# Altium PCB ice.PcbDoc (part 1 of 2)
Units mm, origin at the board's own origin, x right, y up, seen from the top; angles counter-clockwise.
Board outline 65 x 30 mm, 4 copper layers (L1 [TOP], L2 [GND], L3[PWR], L4 [BOTTOM]), stack 1.49 mm thick; 140 components, 110 nets, 478 pads, 226 vias.
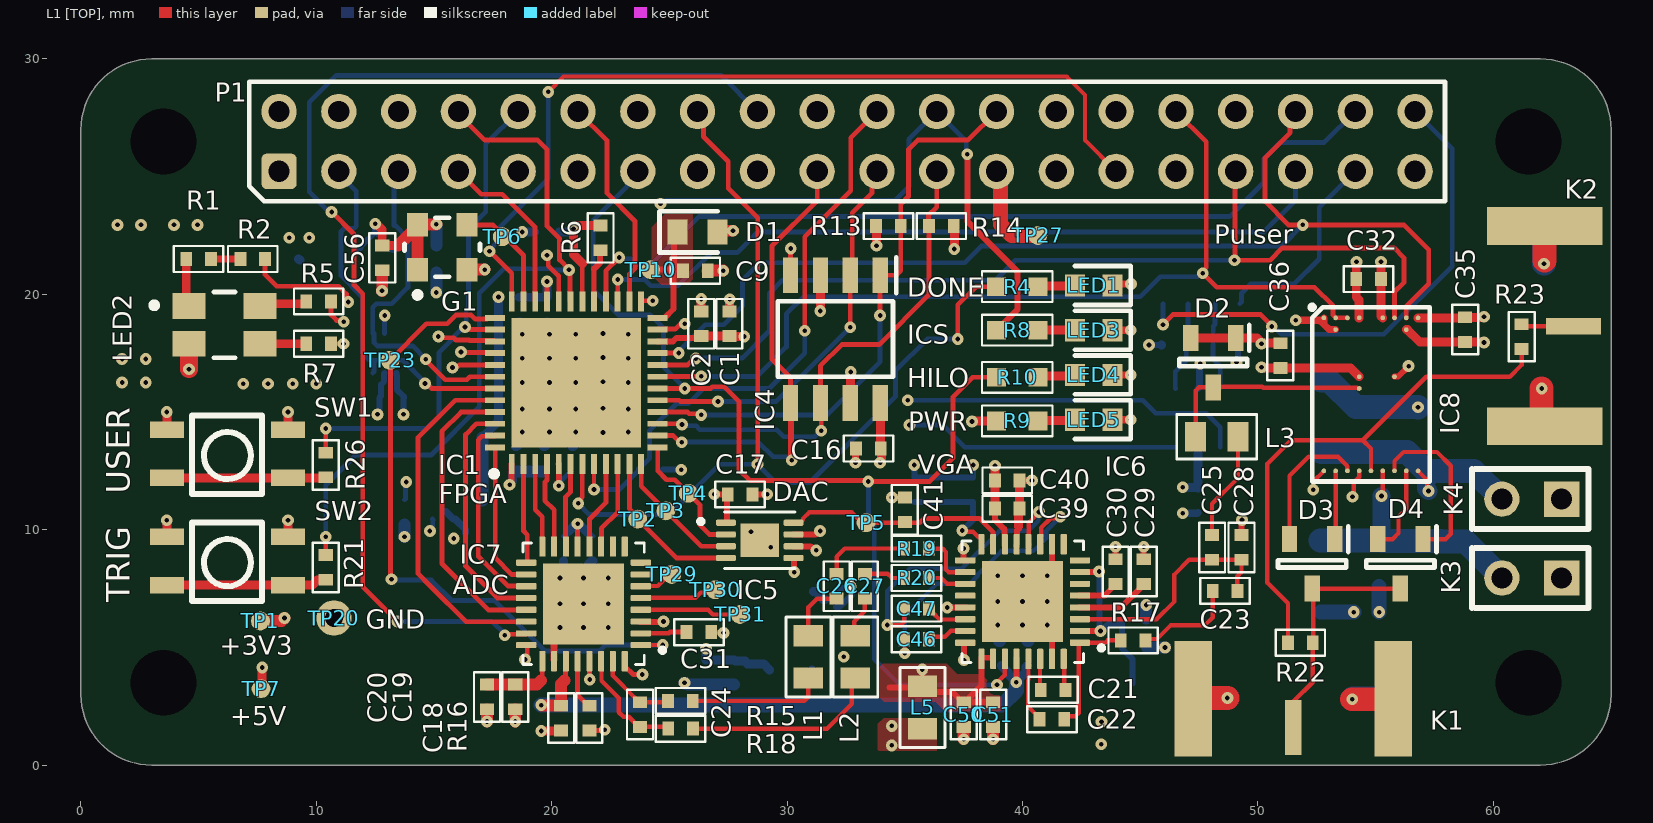
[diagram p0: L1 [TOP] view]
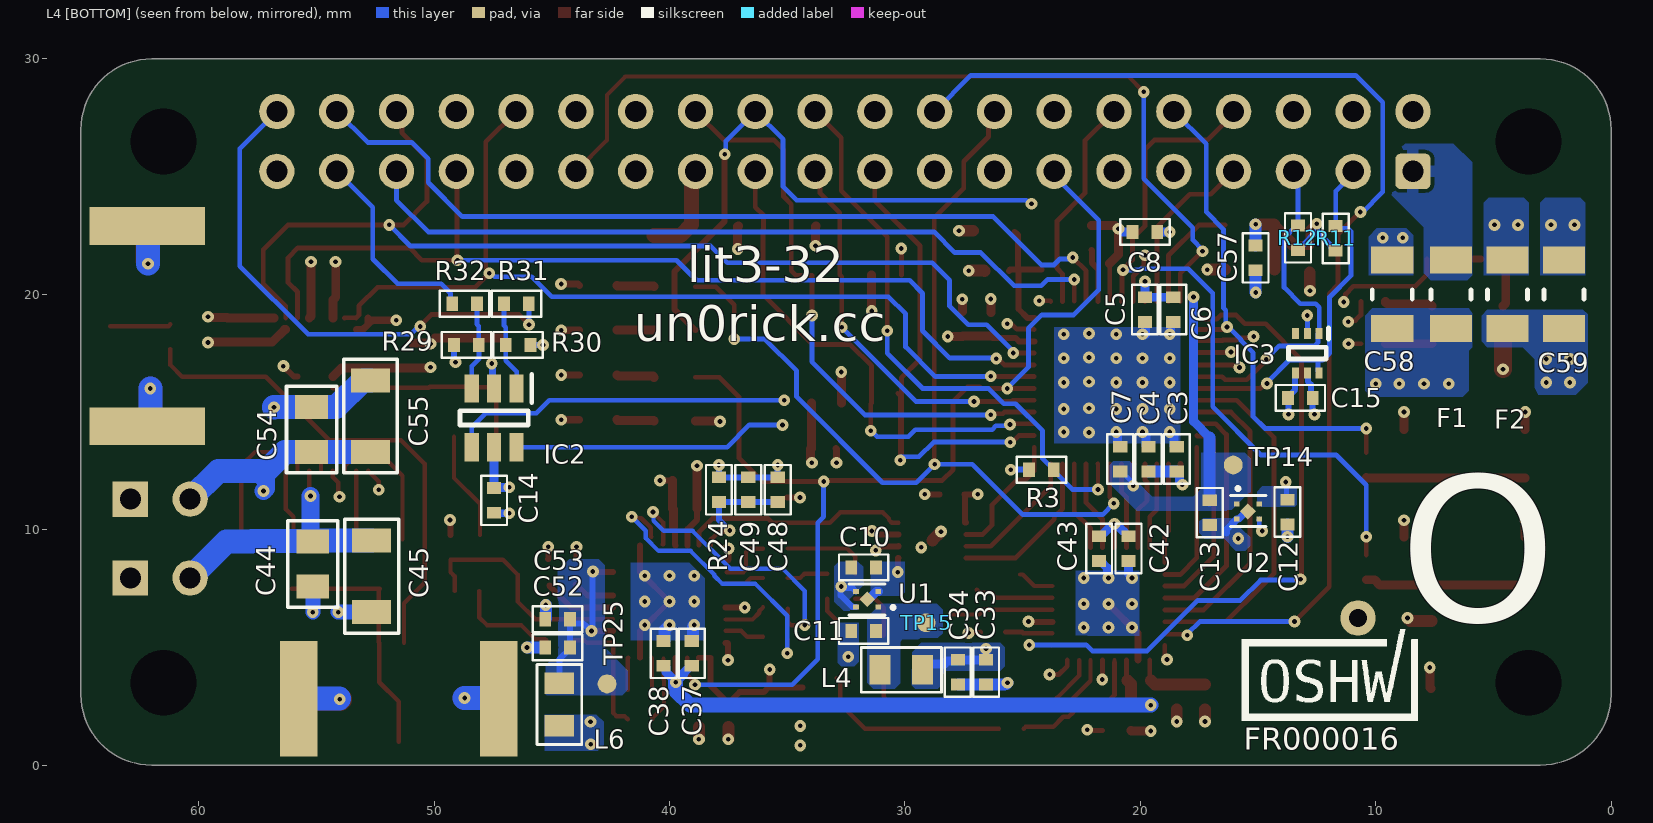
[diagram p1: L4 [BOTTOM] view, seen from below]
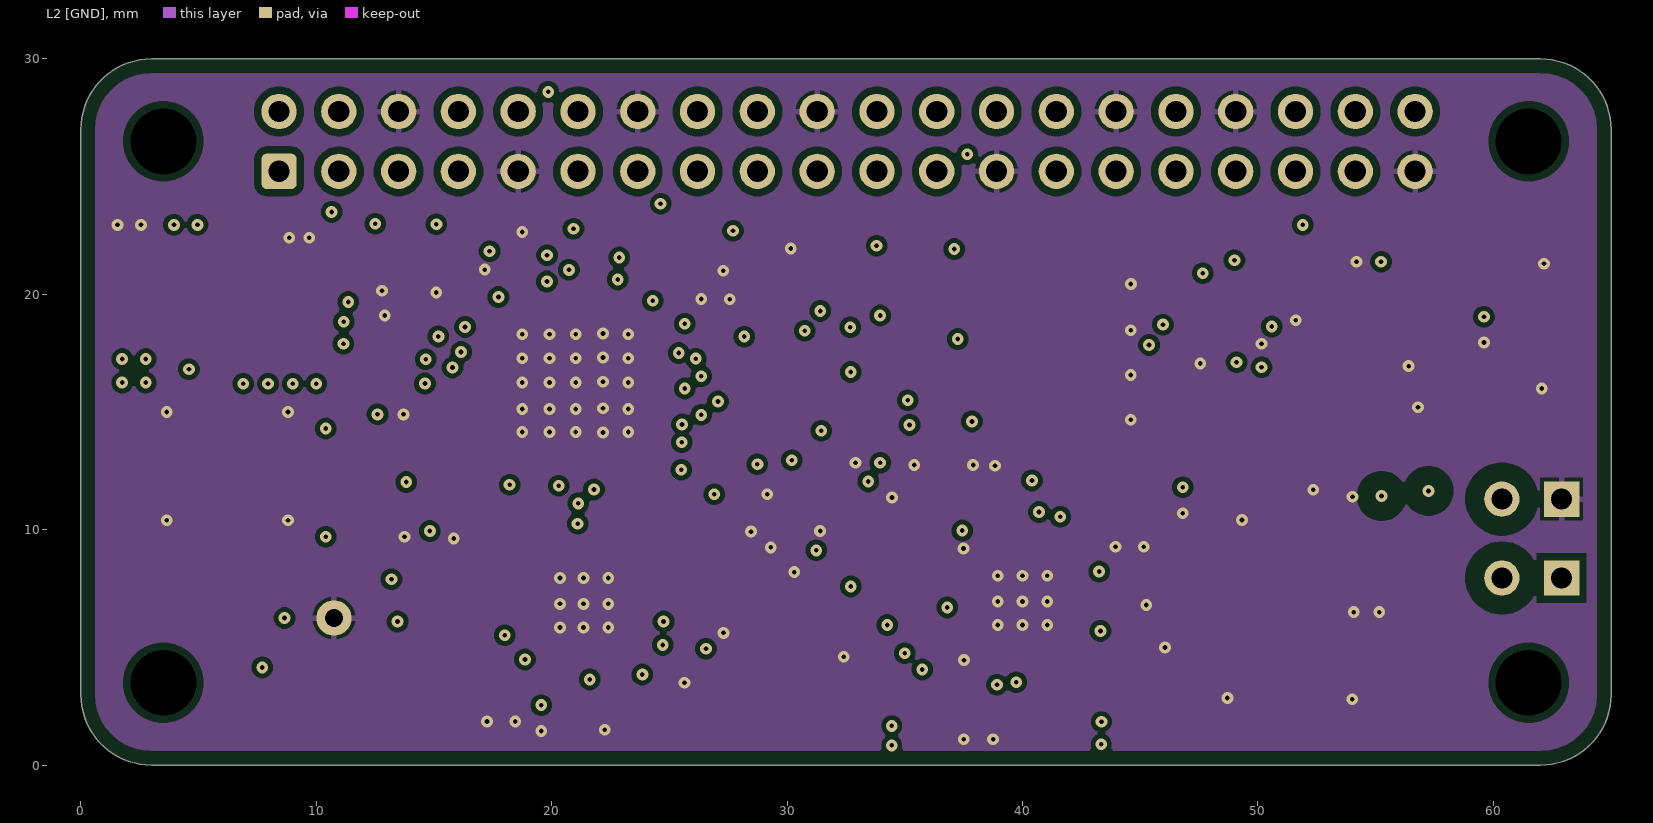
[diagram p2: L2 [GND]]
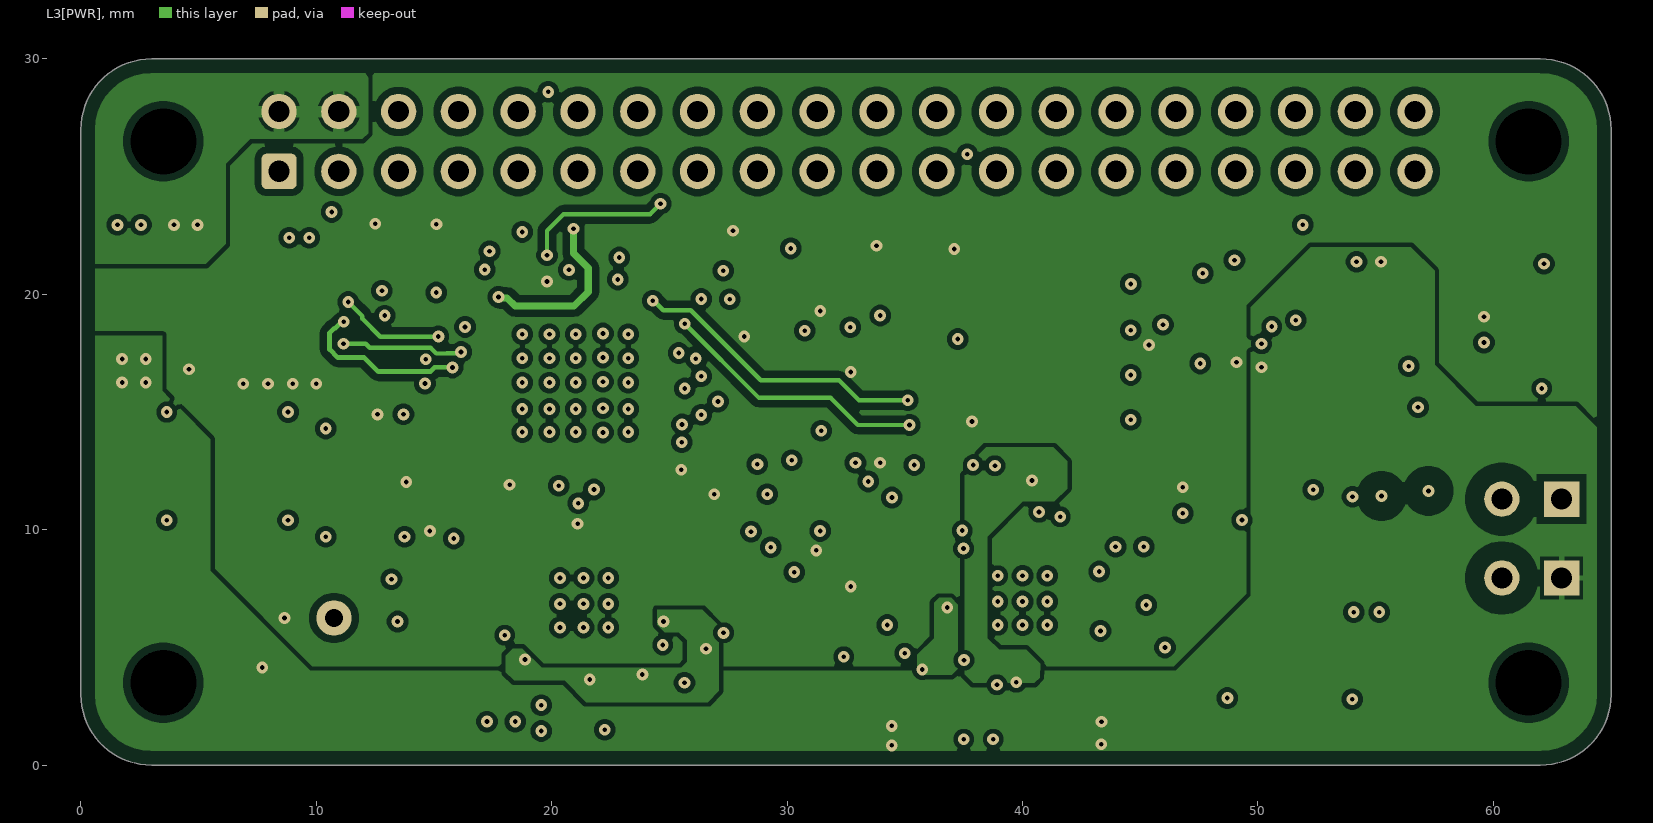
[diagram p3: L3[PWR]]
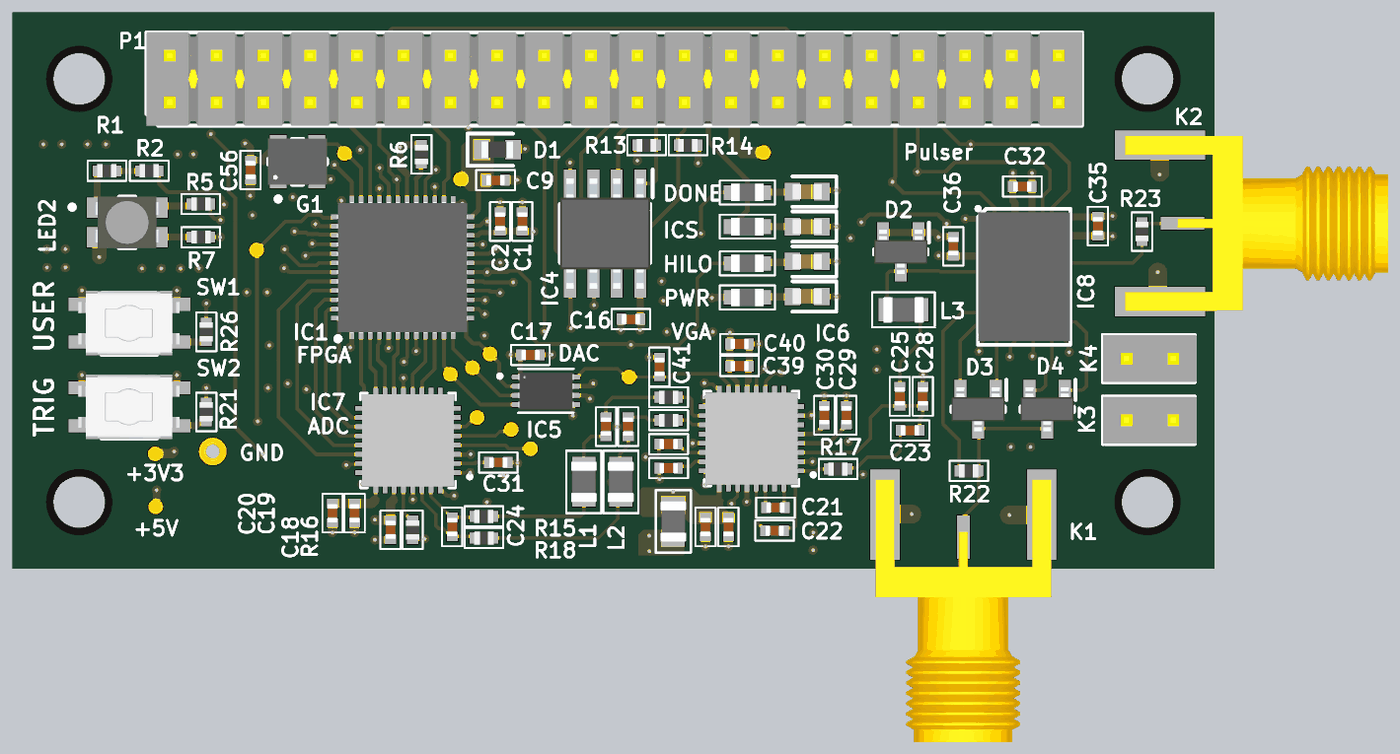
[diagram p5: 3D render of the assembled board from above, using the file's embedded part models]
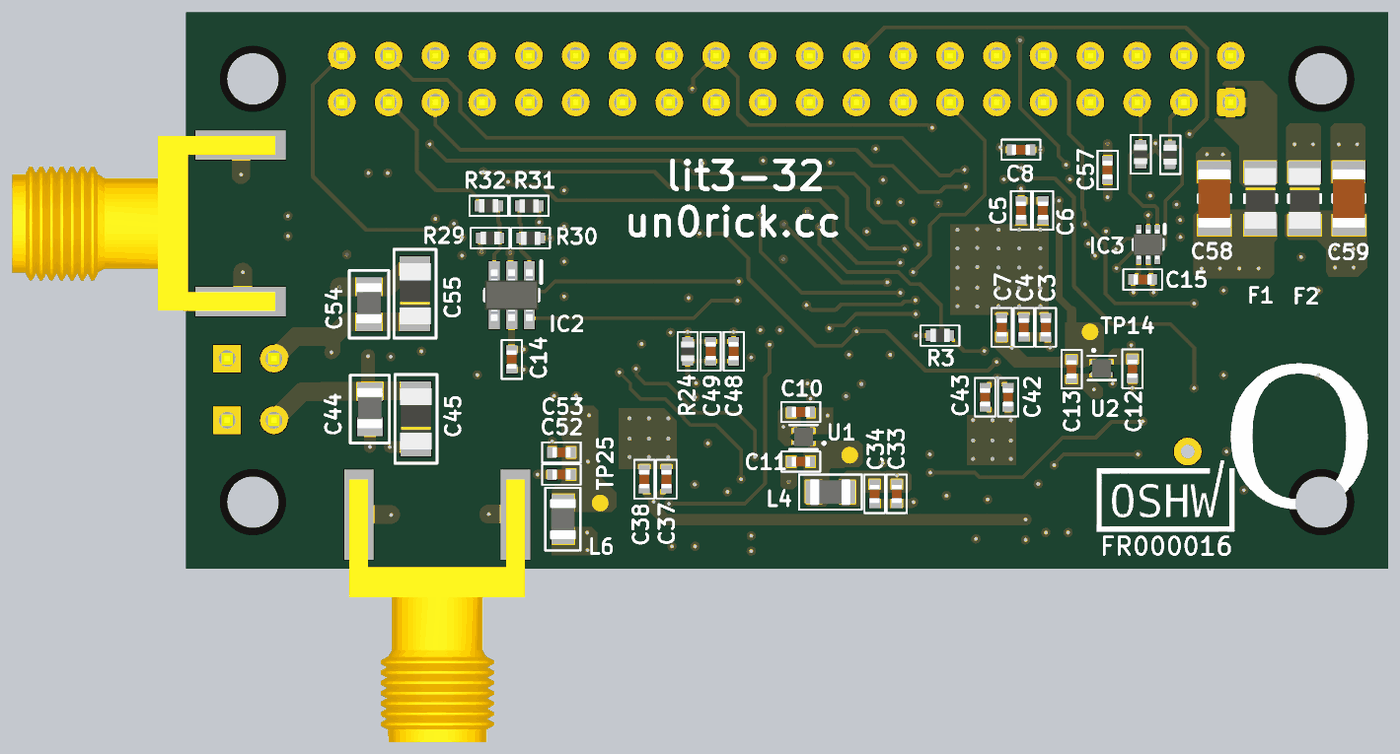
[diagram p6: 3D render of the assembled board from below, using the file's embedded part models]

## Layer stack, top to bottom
Top Solder: solder mask 0.0102, Solder Resist, Dk 3.5
L1 [TOP]: signal copper 0.035
Dielectric 2: prepreg 0.11, PP-018, Dk 4.29
L2 [GND]: signal copper 0.035
Dielectric 1: dielectric 1.13, FR-4, Dk 3.96
L3[PWR]: signal copper 0.035
Dielectric 3: prepreg 0.11, PP-018, Dk 4.29
L4 [BOTTOM]: signal copper 0.035
Bottom Solder: solder mask 0.0102, Solder Resist, Dk 3.5

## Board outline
0,3 0,27 cw(c3,27) 3,30 62,30 cw(c62,27) 65,27 65,3 cw(c62,3) 62,0 3,0 cw(c3,3)

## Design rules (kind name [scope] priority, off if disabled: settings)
BoardOutlineClearance [All] p1: gap=0.2 ignorepadtopadclearanceinfootprint=FALSE except(0.6: Poly-OutlineEdge)
Clearance Clearance_HV [InNet('+HV', '-HV')] p1: gap=0.6 ignorepadtopadclearanceinfootprint=TRUE
Clearance "Clearance Polygons" [InPolygon] p2: gap=0 ignorepadtopadclearanceinfootprint=FALSE except(0.2: Via-Fill Via-Poly Via-Region Fill-Fill Fill-Poly Fill-Region Poly-Poly Poly-Region Region-Region; 0.3: Arc-Fill Arc-Poly Arc-Region Track-Fill Track-Poly Track-Region SMDPad-Fill SMDPad-Poly SMDPad-Region THPad-Fill THPad-Poly THPad-Region)
Clearance [All] p3: gap=0.254 ignorepadtopadclearanceinfootprint=FALSE except(0.15: Arc-Text Track-Text SMDPad-Text THPad-Text Via-Text Fill-Text Poly-Text Region-Text Text-Text; 0.152: Arc-Arc Arc-Track Arc-SMDPad Arc-Via Track-Track Track-SMDPad Track-Via SMDPad-SMDPad SMDPad-Via; 0.2: Via-Fill Via-Poly Via-Region Fill-Fill Fill-Poly Fill-Region Poly-Poly Poly-Region Region-Region; 0.54: THPad-THPad)
ComponentClearance "HM-TRP & UFL" [InComponent('X1') vs InComponent('U1')] p1: gap=0 collisioncheckmode=3 verticalgap=0 showdistances=FALSE
ComponentClearance [All] p2: gap=0.025 collisioncheckmode=3 verticalgap=0.025 showdistances=FALSE
Height [All] p1: minheight=0 maxheight=60 prefheight=12.7
HoleSize [All] p1: absolutevalues=TRUE maxlimit=6.3 minlimit=0.2 maxpercent=80.000 minpercent=20.000
HoleToHoleClearance [All] p1: gap=0.54 allowstackedmicrovias=FALSE
MinimumAnnularRing MinimumAnnularRing_Via [IsVia] p1: minimumring=0.15
MinimumAnnularRing [All] p2: minimumring=0.3
MinimumSolderMaskSliver [All] p1: minsoldermaskwidth=0.1
PlaneClearance [All] p1: clearance=0.254
PlaneConnect [All] p1: planeconnectstyle=Relief reliefexpansion=0.102 reliefentries=4 reliefconductorwidth=0.152 reliefairgap=0.152
PolygonConnect "Via connect style" [isVia] p1: connectstyle=Direct reliefconductorwidth=0.254 reliefentries=4 polygonreliefangle="90 Angle" airgapwidth=0.254
PolygonConnect [All] p2: connectstyle=Relief reliefconductorwidth=0.254 reliefentries=4 polygonreliefangle="90 Angle" airgapwidth=0.152
RoutingCorners [All] p1: cornerstyle=45-Degree minsetback=1.25 maxsetback=1.25
RoutingVias [All] p1: holewidth=0.4 width=0.8 viastyle="Through Hole" minholewidth=0.2 minwidth=0.45 maxholewidth=2 maxwidth=4
SilkToSilkClearance [All] p1: silktosilkclearance=0
SilkToSolderMaskClearance [IsPad] p1: minsilkscreentomaskgap=0.127 clearancetoexposedcopper=TRUE
SolderMaskExpansion SolderMaskExpansion_Via [IsVia] p1: expansion=0.05 istentingtop=TRUE
SolderMaskExpansion [All] p2: expansion=0.05 istentingtop=FALSE useseparateexpansions=TRUE expansionbottom=0.05 istentingbottom=FALSE
UnRoutedNet [All] p1: checkbadconnections=TRUE
Width 50Ohm [InNetClass('50Ohm')] p1 off: maxlimit=0.185 minlimit=0.131 preferedwidth=0.185 toplayer_minwidth=0.185 midlayer1_maxwidth=0.131 midlayer1_prefwidth=0.131 midlayer2_maxwidth=0.131 midlayer2_prefwidth=0.131 bottomlayer_minwidth=0.185 impedanceprofiledriven=TRUE impedanceprofileid={AB148E26-7750-462C-8A86-80EFB9ABE8EF} impedanceprofilevalue=50.000000 minimp=50.000000 maximp=50.000000 favimp=50.000000
Width GND [InNet('GND')] p2: maxlimit=6.35 minlimit=0.127 preferedwidth=0.508
Width [All] p3: maxlimit=10.16 minlimit=0.152 preferedwidth=0.203
19 further rules are at their usual default settings.

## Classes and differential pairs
net class I2C: SCL SDA
net class PCM: PCM_CLK PCM_DIN PCM_FS
net class DAC_SPI: DAC_CS DAC_MOSI DAC_SCLK
net class FLASH_SPI: F_CS F_MISO F_MOSI F_SCLK
net class EA_CLK: EA_CLK
net class DCLK: DCLK
net class ADC_CLK: ADC_CLK
net class 50Ohm: NetC21_1 NetC21_2 NetC22_1 NetC22_2 NetC23_1 NetC23_2 NetC24_1 NetC24_2 NetC25_2 NetC26_1 NetC26_2 NetC27_1 NetC27_2 NetC46_1 NetC46_2 NetC47_1 NetC47_2 NetD2_3 NetD3_3 NetK2_1 NetL1_2 NetL2_2 VOH2 VOL2 XDCR
net class RCLK: RCLK

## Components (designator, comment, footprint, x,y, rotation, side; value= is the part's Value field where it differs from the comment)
C1 "cap0402" SM0402_3D_cap 27.55,18.75 r270 top value=100n
C2 "cap0402" SM0402_3D_cap 26.35,18.75 r270 top value=10u
C3 "cap0402" SM0402_3D_cap 18.45,13 r270 bottom value=100n
C4 "cap0402" SM0402_3D_cap 19.65,13 r270 bottom value=10u
C5 "cap0402" SM0402_3D_cap 19.8,19.35 r90 bottom value=100n
C6 "cap0402" SM0402_3D_cap 18.6,19.35 r90 bottom value=10u
C7 "cap0402" SM0402_3D_cap 20.85,13 r270 bottom value=100n
C8 "cap0402" SM0402_3D_cap 19.8,22.65 r0 bottom value=100n
C9 "cap0402" SM0402_3D_cap 26.1,21 r180 top value=100n
C10 "cap0402" SM0402_3D_cap 31.75,8.4 r0 bottom value=100n
C11 "cap0402" SM0402_3D_cap 31.75,5.7 r180 bottom value=1u
C12 "cap0402" SM0402_3D_cap 13.75,10.75 r90 bottom value=100n
C13 "cap0402" SM0402_3D_cap 17.05,10.725 r90 bottom value=1u
C14 "cap0402" SM0402_3D_cap 47.45,11.25 r90 bottom value=100n
C15 "cap0402" SM0402_3D_cap 13.2,15.6 r0 bottom value=100n
C16 "cap0402" SM0402_3D_cap 33.45,13.45 r180 top value=100n
C17 "cap0402" SM0402_3D_cap 28,11.5 r180 top value=100n
C18 "cap0402" SM0402_3D_cap 20.4,2 r270 top value=100n
C19 "cap0402" SM0402_3D_cap 18.45,2.9 r90 top value=100n
C20 "cap0402" SM0402_3D_cap 17.25,2.9 r90 top value=10u
C21 "cap0402" SM0402_3D_cap 41.3,3.2 r0 top value=100n
C22 "cap0402" SM0402_3D_cap 41.25,1.95 r180 top value=100n
C23 "cap0402" SM0402_3D_cap 48.6,7.4 r180 top value=18n
C24 "cap0402" SM0402_3D_cap 23.75,2.15 r90 top value=18p
C25 "cap0402" SM0402_3D_cap 48.05,9.25 r90 top value=100n
C26 "cap0402" SM0402_3D_cap 32.1,7.6 r90 top value=100n
C27 "cap0402" SM0402_3D_cap 33.3,7.6 r90 top value=100n
C28 "cap0402" SM0402_3D_cap 49.3,9.25 r90 top value=22p
C29 "cap0402" SM0402_3D_cap 45.15,8.225 r90 top value=100n
C30 "cap0402" SM0402_3D_cap 43.95,8.225 r90 top value=100n
C31 "cap0402" SM0402_3D_cap 26.25,5.65 r0 top value=100n
C32 "cap0402" SM0402_3D_cap 54.7,20.65 r180 top value=100n
C33 "cap0402" SM0402_3D_cap 26.55,3.95 r90 bottom value=100n
C34 "cap0402" SM0402_3D_cap 27.75,3.95 r90 bottom value=10u
C35 "cap0402" SM0402_3D_cap 58.8,18.5 r270 top value=100n
C36 "cap0402" SM0402_3D_cap 50.95,17.4 r270 top value=100n
C37 "cap0402" SM0402_3D_cap 39.05,4.75 r270 bottom value=100n
C38 "cap0402" SM0402_3D_cap 40.25,4.75 r270 bottom value=1n
C39 "cap0402" SM0402_3D_cap 39.349,10.895 r0 top value=100n
C40 "cap0402" SM0402_3D_cap 39.349,12.095 r0 top value=1n
C41 "cap0402" SM0402_3D_cap 35,10.85 r270 top value=1n
C42 "cap0402" SM0402_3D_cap 20.5,9.2 r90 bottom value=100n
C43 "cap0402" SM0402_3D_cap 21.75,9.2 r90 bottom value=10u
C44 "cap0805" SM0805 55.15,7.595 r90 bottom value=0.1x200V
C45 "cap1206" SM1206 52.65,6.5 r90 bottom value=0.1x200V
C46 "cap0402" SM0402_3D_cap 35.5,5.35 r0 top value=100n
C47 "cap0402" SM0402_3D_cap 35.5,6.65 r0 top value=100n
C48 "cap0402" SM0402_3D_cap 35.4,11.7 r270 bottom value=100n
C49 "cap0402" SM0402_3D_cap 36.65,11.7 r270 bottom value=1n
C50 "cap0402" SM0402_3D_cap 37.5,2.15 r90 top value=100n
C51 "cap0402" SM0402_3D_cap 38.75,2.15 r90 top value=1n
C52 "cap0402" SM0402_3D_cap 44.75,5 r180 bottom value=100n
C53 "cap0402" SM0402_3D_cap 44.75,6.2 r180 bottom value=1n
C54 "cap0805" SM0805 55.2,13.3 r90 bottom value=0.1x200V
C55 "cap1206" SM1206 52.7,13.3 r90 bottom value=0.1x200V
C56 "cap0402" SM0402_3D_cap 12.8,21.55 r90 top value=100n
C57 "cap0402" SM0402_3D_cap 15.1,21.55 r90 bottom value=10u
C58 "Capacitor" CAP_CERAMIC_1206 9.3,20 r270 bottom value=47uF
C59 "Capacitor" CAP_CERAMIC_1206 2,20 r270 bottom value=47uF
D1 "CDBU0520" DIOC1709X85N 26.2,22.65 r0 top
D2 "MMBD7000HS-7-F" SOT96P240X110-3N 48.1,17.1 r270 top
D3 "MMBD7000HS-7-F" SOT96P240X110-3N 52.3,8.55 r270 top
D4 "MMBD7000HS-7-F" SOT96P240X110-3N 56.05,8.55 r270 top
F1 "1206SFF050F/63-2" FUSE_1206 6.8,20 r270 bottom
F2 "1206SFF050F/63-2" FUSE_1206 4.4,20 r270 bottom
G1 "Oscillator" OSC_ASEM 15.35,22 r0 top
IC1 "ICE40UP5K-SG48ITR" QFN50P700X700X100-49N-D 21.05,16.25 r90 top
IC2 "SN74LVC2G17DBVR" SOT95P280X145-6N 47.45,14.75 r270 bottom
IC3 "TMP112AIDRLR" SOTFL50P160X60-6N 12.9,17.5 r270 bottom
IC4 "W25X10CLSNIG" SOIC127P600X175-8N 32.05,18.1 r270 top
IC5 "MCP4811-E/MC" SON50P200X300X100-9N 28.835,9.55 r0 top
IC6 "AD8332ACPZ-R7" QFN50P500X500X100-33N 40,6.95 r180 top
IC7 "AD9629BCPZ-65" QFN50P500X500X100-33N 21.35,6.85 r180 top
IC8 "HV7361GA-G" BGA22C50P9X14_500X700X105 54.8,15.75 r0 top
K1 "SMA_Edge" AMPHENOL_132357-11 51.5,1.25 r90 top
K2 "SMA_Edge" AMPHENOL_132357-11 63.75,18.65 r180 top
K3 "1x2PLS" JUMPER2 62.9,7.95 r270 top
K4 "1x2PLS" JUMPER2 62.9,11.3 r270 top
L1 "75R@100MHz" "SM_0805_INDUCTANCE _3D" 30.9,4.6 r270 top
L2 "75R@100MHz" "SM_0805_INDUCTANCE _3D" 32.9,4.6 r270 top
L3 "75R@100MHz" "SM_0805_INDUCTANCE _3D" 48.25,13.95 r0 top
L4 "75R@100MHz" "SM_0805_INDUCTANCE _3D" 30.15,4.05 r0 bottom
L5 "75R@100MHz" "SM_0805_INDUCTANCE _3D" 35.75,2.45 r270 top
L6 "75R@100MHz" "SM_0805_INDUCTANCE _3D" 44.675,2.575 r90 bottom
LED1 "HSMW-C191" LEDC1608X70N 43.025,20.375 r180 top
LED2 "CLVBA-FKA-CAEDH8BBB7A363" CLVBAFKACAEDH8BBB7A363 6.1,18.7 r0 top
LED3 "HSMW-C191" LEDC1608X70N 43.025,18.475 r180 top
LED4 "HSMW-C191" LEDC1608X70N 43.025,16.575 r180 top
LED5 "HSMW-C191" LEDC1608X70N 43.025,14.675 r180 top
P1 "2x20 2.54mm vertical" PLD-40 32.545,26.495 r0 top
R1 "100" SM0402_3D_res 5,21.5 r0 top value=4k7
R2 "100" SM0402_3D_res 7.3,21.5 r0 top value=4k7
R3 "10k" SM0402_3D_res 24.2,12.55 r180 bottom value=4k7
R4 "1k" SM0603_3D_res 39.775,20.325 r0 top value=4k7
R5 "100" SM0402_3D_res 10.1,19.7 r0 top value=4k7
R6 "100" SM0402_3D_res 22.075,22.4 r270 top value=4k7
R7 "100" SM0402_3D_res 10.1,17.9 r0 top value=4k7
R8 "1k" SM0603_3D_res 39.775,18.475 r0 top value=4k7
R9 "1k" SM0603_3D_res 39.775,14.625 r0 top value=4k7
R10 "1k" SM0603_3D_res 39.775,16.475 r0 top value=4k7
R11 "4k7" SM0402_3D_res 11.7,22.375 r90 bottom
R12 "4k7" SM0402_3D_res 13.3,22.4 r90 bottom
R13 "4k7" SM0402_3D_res 34.3,22.9 r180 top
R14 "4k7" SM0402_3D_res 36.55,22.9 r180 top
R15 "158" SM0402_3D_res 25.467,2.727 r180 top value=4k7
R16 "10k" SM0402_3D_res 21.6,2 r270 top value=4k7
R17 "280" SM0402_3D_res 44.7,5.3 r180 top value=4k7
R18 "158" SM0402_3D_res 25.475,1.55 r180 top value=4k7
R19 "84,5" SM0402_3D_res 35.5,9.2 r180 top value=4k7
R20 "84,5" SM0402_3D_res 35.5,7.95 r180 top value=4k7
R21 "100" SM0402_3D_res 10.4,8.4 r90 top value=4k7
R22 "0R" SM0402_3D_res 51.8,5.2 r180 top value=4k7
R23 "0R" SM0402_3D_res 61.2,18.2 r90 top value=4k7
R24 "11k" SM0402_3D_res 37.9,11.7 r270 bottom value=4k7
R26 "100" SM0402_3D_res 10.4,12.75 r90 top value=4k7
R29 "4k7" SM0402_3D_res 48.625,17.85 r180 bottom
R30 "4k7" SM0402_3D_res 46.425,17.85 r0 bottom
R31 "100" SM0402_3D_res 46.5,19.6 r0 bottom value=4k7
R32 "100" SM0402_3D_res 48.7,19.6 r180 bottom value=4k7
SW1 "EVQ-P9P02M" "Button 4.7x3.5 _SMT" 3.65,12.2 r90 top
SW2 "EVQ-P9P02M" "Button 4.7x3.5 _SMT" 3.65,7.65 r90 top
TP1 "TP80" TP80_no_silk 7.625,6.125 r0 top
TP2 "TP80" TP80_no_silk 23.65,10.45 r90 top
TP3 "TP80" TP80_no_silk 24.85,10.8 r90 top
TP4 "TP80" TP80_no_silk 25.8,11.55 r90 top
TP5 "TP80" TP80_no_silk 33.35,10.3 r90 top
TP6 "TP80" TP80_no_silk 17.9,22.45 r90 top
TP7 "TP80" TP80_no_silk 7.65,3.25 r90 top
TP10 "TP80" TP80_no_silk 24.2,21.05 r90 top
TP14 "TP80" TP80_no_silk 16.05,12.75 r270 bottom
TP15 "TP80" TP80_no_silk 29.1,6.05 r90 bottom
TP20 "TP125X75" TP125X75 10.75,6.25 r90 top
TP23 "TP80" TP80_no_silk 13.131,17.2 r90 top
TP25 "TP80" TP80_no_silk 42.65,3.45 r0 bottom
TP27 "TP80" TP80_no_silk 40.65,22.5 r90 top
TP29 "TP80" TP80_no_silk 25.1,8.1 r90 top locked
TP30 "TP80" TP80_no_silk 26.95,7.45 r90 top locked
TP31 "TP80" TP80_no_silk 28,6.4 r90 top
U1 "TLV70718PDQNR" "X2SON - 2" 31.601,7.046 r0 bottom
U2 "TLV70712PDQNR" "X2SON - 2" 15.425,10.775 r180 bottom

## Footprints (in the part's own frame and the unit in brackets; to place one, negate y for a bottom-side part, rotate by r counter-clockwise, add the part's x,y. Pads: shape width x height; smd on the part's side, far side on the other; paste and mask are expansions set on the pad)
AMPHENOL_132357-11 [mm]
  rect 2.35x0.7 smd: 1(0.35,0)
  rect 4.9x1.6 smd: 2(1.575,4.25) 2(1.575,-4.25)
  rect 4.9x1.6 smd far side: 2(1.575,4.25) 2(1.575,-4.25)
  body extent -10.8,-4.76 3.48,4.76, height 4.08
BGA22C50P9X14_500X700X105 [mm]
  round 0.2 smd: A1(-2,3.25) A2(-1.5,3.25) A3(-1,3.25) A4(-0.5,3.25) A6(0.5,3.25) A7(1,3.25) A8(1.5,3.25) A9(2,3.25) B2(-1.5,2.75) B8(1.5,2.75) F4(-0.5,0.75) F7(1,0.75) G4(-0.5,0.25) P1(-2,-3.25) P2(-1.5,-3.25) P3(-1,-3.25) P4(-0.5,-3.25) P5(0,-3.25) P6(0.5,-3.25) P7(1,-3.25) P8(1.5,-3.25) P9(2,-3.25)
  silkscreen extent -2.6,-3.7 2.5,3.8, body extent -2.5,-3.5 2.5,3.5, height 1.05
"Button 4.7x3.5 _SMT" [mm] "EVQ-P9P02M_SMT"
  rect 0.7x1.45 smd: 1(0,0) 2(0,-5.15) 3(2.05,0) 4(2.05,-5.15)
  silkscreen extent -0.67,-4.05 2.65,-1.07, body extent -0.72,-5.3 2.78,0.2, height 2.11
CAP_CERAMIC_1206 [mm]
  rect 1.15x1.8 smd mask+0.051: 1(-1.45,0) 2(1.45,0)
  silkscreen extent -0.2,-0.85 0.2,0.85, body extent -1.6,-0.9 1.6,0.9, height 1.61
CLVBAFKACAEDH8BBB7A363 [mm]
  rect 1.4x1.1 smd: 1(-1.5,0.8) 2(-1.5,-0.8) 3(1.5,0.8) 4(1.5,-0.8)
  silkscreen extent -3.11,-1.4 0.45,1.4, body extent -1.75,-1.4 1.75,1.4, height 2.06
DIOC1709X85N [mm]
  rect 0.85x1.05 smd: 1(-0.85,0) 2(0.85,0)
  silkscreen extent -1.63,-0.87 0.85,0.87, body extent -0.85,-0.45 0.85,0.45, height 0.85
FUSE_1206 [mm] "FUSE, 2-Leads, Body 3.2x1.60mm, IPC Medium Density"
  rect 1.15x1.8 smd mask+0.051: 1(-1.45,0) 2(1.45,0)
  silkscreen extent -0.2,-0.85 0.2,0.85, body extent -1.65,-0.85 1.65,0.85, height 0.61
JUMPER2 [mm]
  rect 1.5x1.5 hole 0.9: 1(0,0)
  round 1.5 hole 0.9: 2(0,-2.54)
  silkscreen extent -1.27,-3.81 1.27,1.14, body extent -1.27,-3.81 1.27,1.27, height 8.39
LEDC1608X70N [mm]
  rect 0.85x0.95 smd: 1(-0.8,0) 2(0.8,0)
  silkscreen extent -1.58,-0.82 0.8,0.82, body extent -0.8,-0.41 0.8,0.41, height 0.61
OSC_ASEM [mm]
  rect 0.9x1 smd mask+0.051: 1(-1.05,-0.95) 2(1.05,-0.95) 3(1.05,0.95) 4(-1.05,0.95)
  silkscreen extent -1.6,-2.15 1.6,1.25, body extent -1.6,-1.25 1.6,1.25, height 0.85
PLD-40 [mm]
  rrect30% 1.5x1.5 hole 0.9: 1(-24.13,-1.27)
  round 1.5 hole 0.9: 2(-24.13,1.27) 3(-21.59,-1.27) 4(-21.59,1.27) 5(-19.05,-1.27) 6(-19.05,1.27) 7(-16.51,-1.27) 8(-16.51,1.27) 9(-13.97,-1.27) 10(-13.97,1.27) 11(-11.43,-1.27) 12(-11.43,1.27) 13(-8.89,-1.27) 14(-8.89,1.27) 15(-6.35,-1.27) 16(-6.35,1.27) 17(-3.81,-1.27) 18(-3.81,1.27) 19(-1.27,-1.27) 20(-1.27,1.27) 21(1.27,-1.27) 22(1.27,1.27) 23(3.81,-1.27) 24(3.81,1.27) 25(6.35,-1.27) 26(6.35,1.27) 27(8.89,-1.27) 28(8.89,1.27) 29(11.43,-1.27) 30(11.43,1.27) 31(13.97,-1.27) 32(13.97,1.27) 33(16.51,-1.27) 34(16.51,1.27) 35(19.05,-1.27) 36(19.05,1.27) 37(21.59,-1.27) 38(21.59,1.27) 39(24.13,-1.27) 40(24.13,1.27)
  silkscreen extent -25.4,-2.54 25.4,2.54, body extent -25.4,-2.54 25.4,2.54, height 8.39
QFN50P500X500X100-33N [mm]
  rrect25% 0.86x0.26 smd: 1(-2.435,1.75) 2(-2.435,1.25) 3(-2.435,0.75) 4(-2.435,0.25) 5(-2.435,-0.25) 6(-2.435,-0.75) 7(-2.435,-1.25) 8(-2.435,-1.75) 17(2.435,-1.75) 18(2.435,-1.25) 19(2.435,-0.75) 20(2.435,-0.25) 21(2.435,0.25) 22(2.435,0.75) 23(2.435,1.25) 24(2.435,1.75)
  rrect25% 0.26x0.86 smd: 9(-1.75,-2.435) 10(-1.25,-2.435) 11(-0.75,-2.435) 12(-0.25,-2.435) 13(0.25,-2.435) 14(0.75,-2.435) 15(1.25,-2.435) 16(1.75,-2.435) 25(1.75,2.435) 26(1.25,2.435) 27(0.75,2.435) 28(0.25,2.435) 29(-0.25,2.435) 30(-0.75,2.435) 31(-1.25,2.435) 32(-1.75,2.435)
  rect 3.45x3.45 smd paste-3: 33(0,0)
  silkscreen extent -3.45,-2.58 2.58,2.58, body extent -2.52,-2.52 2.52,2.52, height 0.88
QFN50P700X700X100-49N-D [mm]
  rect 0.85x0.25 smd mask+0.025: 1(-3.45,2.75) 12(-3.45,-2.75) 25(3.45,-2.75) 36(3.45,2.75)
  rect 0.85x0.25 smd: 2(-3.45,2.25) 3(-3.45,1.75) 4(-3.45,1.25) 5(-3.45,0.75) 6(-3.45,0.25) 7(-3.45,-0.25) 8(-3.45,-0.75) 9(-3.45,-1.25) 10(-3.45,-1.75) 11(-3.45,-2.25) 26(3.45,-2.25) 27(3.45,-1.75) 28(3.45,-1.25) 29(3.45,-0.75) 30(3.45,-0.25) 31(3.45,0.25) 32(3.45,0.75) 33(3.45,1.25) 34(3.45,1.75) 35(3.45,2.25)
  rect 0.25x0.85 smd mask+0.025: 13(-2.75,-3.45) 24(2.75,-3.45) 37(2.75,3.45) 48(-2.75,3.45)
  rect 0.25x0.85 smd: 14(-2.25,-3.45) 15(-1.75,-3.45) 16(-1.25,-3.45) 17(-0.75,-3.45) 18(-0.25,-3.45) 19(0.25,-3.45) 20(0.75,-3.45) 21(1.25,-3.45) 22(1.75,-3.45) 23(2.25,-3.45) 38(2.25,3.45) 39(1.75,3.45) 40(1.25,3.45) 41(0.75,3.45) 42(0.25,3.45) 43(-0.25,3.45) 44(-0.75,3.45) 45(-1.25,3.45) 46(-1.75,3.45) 47(-2.25,3.45)
  rect 5.5x5.5 smd: 49(0,0)
  silkscreen extent -4,3.37 -3.75,3.62, body extent -3.55,-3.55 3.55,3.55, height 1
SM0402_3D_cap [mm] "0402 cap"
  rect 0.5x0.6 smd: 1(-0.525,0) 2(0.525,0)
  silkscreen extent -1.05,-0.55 1.05,0.55, body extent -0.5,-0.27 0.5,0.28, height 0.51
SM0402_3D_res [mm] "0603 inch resistor"
  rect 0.5x0.6 smd: 1(-0.525,0) 2(0.525,0)
  silkscreen extent -1.05,-0.55 1.05,0.55, body extent -0.52,-0.35 0.53,0.36, height 0.51
SM0603_3D_res [mm] "0603 inch resistor"
  rect 0.8x0.8 smd: 1(-0.875,0) 2(0.875,0)
  silkscreen extent -1.5,-0.65 1.5,0.65, body extent -0.87,-0.47 0.88,0.48, height 0.55
SM0805 [mil]
  rect 40x55 smd: 1(0,0) 2(75,0)
  silkscreen extent -35,-42 110,42, body extent -3,-28 83,28, height 43
SM1206 [mil]
  rect 40x65 smd: 1(0,0) 2(120,0)
  silkscreen extent -35,-45 155,45, body extent -5,-34 125,34, height 24
"SM_0805_INDUCTANCE _3D" [mm] "chip inductanse 0805 inch"
  rect 0.9x1.25 smd: 1(-0.9,0) 2(0.9,0)
  silkscreen extent -1.7,-0.95 1.7,0.95, body extent -1.1,-0.7 1.1,0.7, height 1.1
SOIC127P600X175-8N [mm]
  rect 1.525x0.65 smd: 1(-2.712,1.905) 2(-2.712,0.635) 3(-2.712,-0.635) 4(-2.712,-1.905) 5(2.712,-1.905) 6(2.712,-0.635) 7(2.712,0.635) 8(2.712,1.905)
  silkscreen extent -3.47,-2.45 1.6,2.58, body extent -3,-2.45 3,2.45, height 1.75
SON50P200X300X100-9N [mm]
  rrect50% 0.84x0.27 smd: 1(-1.435,0.75) 2(-1.435,0.25) 3(-1.435,-0.25) 4(-1.435,-0.75) 5(1.435,-0.75) 6(1.435,-0.25) 7(1.435,0.25) 8(1.435,0.75)
  rect 1.625x1.425 smd paste-2: 9(0,0)
  silkscreen extent -2.6,-1.2 1.5,1.2, body extent -1.5,-1.01 1.5,1, height 0.94
SOT95P280X145-6N [mm]
  rect 1.2x0.6 smd: 1(-1.25,0.95) 2(-1.25,0) 3(-1.25,-0.95) 4(1.25,-0.95) 5(1.25,0) 6(1.25,0.95)
  silkscreen extent -1.85,-1.45 0.3,1.6, body extent -1.4,-1.45 1.4,1.45, height 1.45
SOT96P240X110-3N [mm]
  rect 1.1x0.65 smd: 1(-1.05,0.96) 2(-1.05,-0.96) 3(1.05,0)
  silkscreen extent -1.6,-1.45 0.15,1.54, body extent -1.2,-1.45 1.2,1.45, height 1.1
SOTFL50P160X60-6N [mm]
  rect 0.475x0.3 smd: 1(-0.838,0.5) 2(-0.838,0) 3(-0.838,-0.5) 4(0.838,-0.5) 5(0.838,0) 6(0.838,0.5)
  silkscreen extent -1.07,-0.8 0.25,0.9, body extent -0.8,-0.8 0.8,0.8, height 0.6
TP80_no_silk [mm]
  round 0.8 smd paste-10 mask+0.051: 1(0,0)
TP125X75 [mm]
  round 1.5 hole 0.75: 1(0,0)
"X2SON - 2" [mm] "DQN, X2SON"
  rect 0.24x0.21 smd paste+0 mask+0.08: 1(-0.475,0.325) 2(-0.475,-0.325) 3(0.475,-0.325) 4(0.475,0.325)
  rect 0.48x0.48 smd rot 45 mask+0.075: 5(0,0)
  silkscreen extent -1.17,-0.65 0.78,0.68, body extent -0.5,-0.5 0.5,0.5, height 0.37

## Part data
C1 C2 C3 C4 C5 C6 C7 C8 C9 C10 C11 C12 C13 C14 C15 C16 C17 C18 C19 C20 C21 C22 C23 C24 C25 C26 C27 C28 C29 C30 C31 C32 C33 C34 C35 C36 C37 C38 C39 C40 C41 C42 C43 C46 C47 C48 C49 C50 C51 C52 C53 C56 C57: "Capacitor  0402 inch"
C44 C45 C54 C55: "Capacitor"
C58 C59: "CAP CER 47UF 25V X5R 1206", ATT Capacitor Type=Ceramic, ATT Case="1206 (3216 Metric)", ATT Lifetime @ Temp=-, ATT Operating Temperature="-25°C ~ 85°C", ATT Temperature Coefficient=JB, ATT Tolerance=±20%, ATT Working Voltage=25V, DigikeyPartNumber=445-11717-1-ND, ManufacturerPartNumber=C3216JB1E476M160AC
D1: "Schottky Diode", Manufacturer_Name="Comchip Technology", Mouser Part Number=750-CDBU0520
D2 D3 D4: "Diode", Manufacturer_Name="Diodes Inc.", Mouser Part Number=621-MMBD7000HS-7-F
F1 F2: "500mA AC 63V DC Fuse Board Mount Surface Mount 1206", ATT Current Rating (Amps)=500mA, ATT Operating Temperature="-55°C ~ 125°C", ATT Voltage Rating DC=63V, DigikeyPartNumber=1206SFF050F/63-2CT-ND
G1: "OSC MEMS 80 MHZ SMD", ATT Frequency=80Mhz, ATT Frequency Stability=±10ppm, ATT Operating Temperature="-40°C ~ 85°C", ATT Package / Case="4-SMD, No Lead (DFN, LCC)", ATT Supply Current=16mA, ATT Supply Voltage="1.7 V ~ 3.6 V", Supplier Part Number 1=535-11082-1-ND
IC1: "Integrated Circuit", Manufacturer_Name="Lattice Semiconductor", Mouser Part Number=842-40UP5KSG48ITR
IC2: "Integrated Circuit", Manufacturer_Name="Texas Instruments", Mouser Part Number=595-SN74LVC2G17DBVR
IC3: "Integrated Circuit", Manufacturer_Name="Texas Instruments", Mouser Part Number=595-TMP112AIDRLR
IC4: "Integrated Circuit", Manufacturer_Name=Winbond, Mouser Part Number=454-W25X10CLSNIG
IC5: "DAC 1-CH Resistor-String 10-bit Automotive 8-Pin DFN EP Tube", Case/Package=DFN, Input Offset Voltage (Vos)=820uV, Manufacturer=Microchip, Max Operating Temperature=125°C, Max Supply Voltage=5.5V, Min Operating Temperature=-40°C, Min Supply Voltage=2.7V, Nominal Supply Current=330uA, Operating Supply Voltage=5V, Package Quantity=150, Supplier Part Number 1=MCP4811-E/MC-ND
IC6: "Integrated Circuit", Manufacturer_Name="Analog Devices", Mouser Part Number=584-AD8332ACPZ-R7
IC7: "Integrated Circuit", Manufacturer_Name="Analog Devices", Mouser Part Number=584-AD9629BCPZ-65
IC8: "Integrated Circuit", Manufacturer_Name=Microchip, Mouser Part Number=579-HV7361GA-G
L1 L2: "chip inductance", Case=0805, Manufacturer=MURATA, Manufacturer Part Number=AIML-0805HC-1R5M-T, Part Number=IND0805_MURATA_BLM21BB750SN1D, Power=700mA, Resistance=0.16R, Supplier Part Number 1=535-12788-1-ND, Tolerance=±25%
L3 L4 L5 L6: "Ferrite Beads Multi-Layer 600Ohm 25% 100MHz 1A 0.2Ohm DCR 0603 T/R", Case=0805, Case/Package=0603, Manufacturer=MURATA, Manufacturer Part Number=BLM21BB750SN1D, ManufacturerPartNumber=PBY160808T-601Y-N, Part Number=IND0805_MURATA_BLM21BB750SN1D, Power=700mA, Resistance=0.16R, Supplier Part Number 1=13-PBY160808T-601Y-NCT-ND, Tolerance=±25%
LED1 LED3 LED4 LED5: "LED", Manufacturer_Name="Avago Technologies", Mouser Part Number=630-HSMW-C191
LED2: "LED", Manufacturer_Name=Cree, Mouser Part Number=941-VBAFKACAEDH8B7A3
P1: "Header, 40-Pin"
R1 R2 R3 R5 R6 R7 R11 R12 R13 R14 R15 R16 R17 R18 R19 R20 R21 R22 R23 R24 R26 R29 R30 R31 R32: "Res_0402_EU", Case=1206, Manufacturer=GENERIC, Manufacturer1 ComponentHeight=0.65mm, Manufacturer1 Example="NIC COMPONENT", Manufacturer1 Part Number=NRC12F4701TRF, Manufacturer Part Number=R1206_4K7_1%_0.25W_100PPM, Power=0.25W, Tolerance=±1%
R4 R8 R9 R10: "Res_0603_EU", Case=1206, Manufacturer=GENERIC, Manufacturer1 ComponentHeight=0.65mm, Manufacturer1 Example="NIC COMPONENT", Manufacturer1 Part Number=NRC12F4701TRF, Manufacturer Part Number=R1206_4K7_1%_0.25W_100PPM, Power=0.25W, Tolerance=±1%
SW1 SW2: library part "Button 4.7x3.5 SMT"
U1 U2: "low drop LDO"

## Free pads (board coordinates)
  round 0 hole 2.8 unplated mask+1.8: 0(3.5,3.5) 0(3.5,26.5) 0(61.5,3.5) 0(61.5,26.5)

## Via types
v1: diameter 0.5, hole 0.2, L1 [TOP] to L4 [BOTTOM], tented both sides, 226 vias

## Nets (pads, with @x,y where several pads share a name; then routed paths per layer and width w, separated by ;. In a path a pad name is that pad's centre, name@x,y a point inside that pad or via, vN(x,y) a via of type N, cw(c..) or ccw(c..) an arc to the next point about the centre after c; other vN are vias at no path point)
0V9: C18.1 C37.2 C38.2 C39.2 C40.2 IC6.13 IC6.28 IC7.27 | length 30
  L1 [TOP] w0.203: 20.546,3.6 20.588,3.642 IC7.27@20.588,4.462
  L1 [TOP] w0.254: v1(19.55,2.55) v1@19.575,2.525 ; v1(39.736,3.517) 39.747,3.528 39.747,4.56 IC6.28@39.748,4.561 ; IC6.13@39.746,9.338 39.771,9.363 39.771,9.984 39.874,10.087 ; C40.2@39.874,12.095 v1(40.399,12.095)
  L1 [TOP] w0.381: 39.833,10.128 39.833,10.854 C39.2@39.874,10.895 C40.2@39.874,12.095
  L1 [TOP] w0.508: v1@19.575,2.525 C18.1@20.4,2.525 20.4,3.454 20.546,3.6
  L4 [BOTTOM] w0.254: C37.2@39.05,4.225 C37.2@39.1,4.225 ; C38.2@40.2,4.225 C38.2@40.25,4.225
  L4 [BOTTOM] w0.381: C37.2@39.1,4.225 39.378,3.946 39.378,3.885 39.747,3.517 39.747,3.559 40.14,3.953 40.14,4.165 C38.2@40.2,4.225
  L4 [BOTTOM] w0.635: v1(19.55,2.55) 39.122,2.55 39.747,3.175 39.736,3.185 v1(39.736,3.517)
5VLNA: C52.2 C53.2 IC6.2 IC6.7 L6.2 TP25.1 | length 8.3
  L1 [TOP] w0.254: IC6.2@42.388,5.703 42.39,5.7 v1@43.309,5.7 ; IC6.7@42.388,8.195 43.145,8.195 43.175,8.225 v1(43.252,8.225)
  L4 [BOTTOM] w0.254: v1(43.252,8.225) 43.276,8.201 43.276,5.735 v1(43.31,5.701) ; v1@43.31,5.736 43.376,5.736 43.602,5.962 43.617,5.962 43.683,6.027 44.102,6.027 C53.2@44.225,6.15 ; C53.2@44.225,6.2 C53.2@44.225,6.15 ; L6.2@44.675,3.475 44.675,4.5 44.225,4.95 C52.2@44.225,5 44.225,6.027 C53.2@44.225,6.15
5VVGA: C50.2 C51.2 IC6.21 IC6.25 IC6.26 L5.1 | length 8.9
  L1 [TOP] w0.254: 34.35,3.3 35.7,3.3 L5.1@35.75,3.35 ; v1@35.75,4.02 L5.1@35.75,3.35 ; v1(36.8,6.7) 37.608,6.7 IC6.21@37.612,6.696 ; C51.2@38.75,2.675 C50.2@37.55,2.675 ; IC6.26@38.753,4.56 38.755,4.562 38.247,4.562 38.247,3.373 C50.2@37.55,2.675 ; L5.1@35.75,3.35 36,3.1 37.025,3.1 37.45,2.675 C50.2@37.5,2.675 C50.2@37.55,2.675
  other v1: 35.74,4.063
+1V2: C7.2 C8.2 C13.2 IC1.5 IC1.30 R6.1 TP14.1 U2.1 | length 23
  L1 [TOP] w0.203: IC1.5@20.293,12.793 IC1.5@20.3,12.8 ; IC1.30@21.3,19.7 21.3,21.312
  L1 [TOP] w0.254: IC1.5@20.293,12.793 20.299,12.788 v1(20.299,11.873)
  L1 [TOP] w0.381: 21.3,21.312 20.918,21.694 20.923,21.699 v1(20.923,22.788) 20.944,22.788 21.081,22.925 R6.1@22.075,22.925
  L3[PWR] w0.305: v1(17.737,19.885) 17.774,19.848 18.102,19.848 18.45,19.5 20.95,19.5 21.55,20.1 21.55,21.12 20.923,21.747 v1(20.923,22.788)
  L4 [BOTTOM] w0.203: v1(20.299,11.873) 20.356,11.93 20.356,12.031 20.8,12.475 C7.2@20.85,12.475
  L4 [BOTTOM] w0.381: 17.05,13.913 17.737,14.6 v1(17.737,19.885) ; C8.2@20.325,22.65 20.763,22.65 20.901,22.788 v1(20.923,22.788)
  L4 [BOTTOM] w0.508: C13.2@17.05,11.25 17.05,13.913
+1V2PLL: IC1.29 R6.2 | length 2.3
  L1 [TOP] w0.203: IC1.29@21.8,19.7 21.8,21.05
  L1 [TOP] w0.254: 21.8,21.05 21.8,21.091 22.055,21.346 22.055,21.854 R6.2@22.075,21.875
+1V8: C11.2 L4.2 TP15.1 U1.1 | length 0
+1V8f: C33.2 C34.2 IC7.3 IC7.24 IC7.29 IC7.32 L4.1 | length 7
  L1 [TOP] w0.203: v1(18.861,4.488) 18.962,4.589 IC7.24@18.962,5.097 ; IC7.29@21.604,4.462 21.608,4.458 21.608,3.644 v1(21.612,3.64) ; IC7.32@23.103,4.462 23.103,4.208 23.461,3.85 v1(23.85,3.85) ; v1@24.738,6.088 v1(24.75,6.1)
  L1 [TOP] w0.254: IC7.3@23.738,6.088 v1@24.738,6.088
  L4 [BOTTOM] w0.381: v1(26.55,4.948) C33.2@26.55,4.475 C34.2@27.75,4.475 27.81,4.416 28.201,4.416 28.317,4.299 29.001,4.299 L4.1@29.25,4.05
+2V5: C9.2 D1.1 IC1.24 TP10.1 | length 5.6
  L1 [TOP] w0.254: TP10.1@24.2,21.05 25.125,21.05 ; IC1.24@24.5,19 24.796,19 25.175,19.379 25.175,21 25.125,21.05 ; D1.1@25.35,22.65 25.3,22.6 25.275,22.6 25.2,22.525 25.2,21.125 25.125,21.05 ; C9.2@25.575,21 25.525,21.05 25.125,21.05
+3V3: C1.2 C2.2 C3.2 C4.2 C5.2 C6.2 C10.2 C12.2 C14.2 C15.1 C16.1 C17.2 C35.1 C42.2 C43.2 C56.2 C57.2 C58.2 D1.2 F1.2 G1.1 G1.4 IC1.1 IC1.22 IC1.33 IC2.5 IC3.5 IC4.3 IC4.7 IC4.8 IC5.1 IC5.6 IC7.13 IC8.A9 LED2.2 R3.1 R9.1 R11.1 R12.1 R13.2 R14.1 R29.1 R30.1 TP1.1 U1.3 U1.4 U2.3 U2.4 | length 47.6
  L1 [TOP] w0.203: v1(19.796,20.543) 19.798,20.541 19.798,19.702 IC1.33@19.8,19.7 ; IC7.13@21.096,9.238 21.096,10.246 v1(21.1,10.25)
  L1 [TOP] w0.254: v1(18.211,11.909) 18.211,11.975 18.298,12.062 18.298,12.798 IC1.1@18.3,12.8 ; IC1.22@24.5,18 24.502,18.002 25.15,18.002 25.291,18.142 26.267,18.142 C2.2@26.35,18.225 ; v1(26.907,11.507) 26.911,11.504 27.471,11.504 C17.2@27.475,11.5 ; D1.2@27.05,22.65 D1.2@27.1,22.7 ; IC5.1@27.4,10.3 27.429,10.3 27.437,10.308 C17.2@27.437,11.462 ; C1.2@27.529,18.225 27.55,18.204 C1.2@27.56,18.215 ; v1@28.163,18.215 v1(28.174,18.204) ; IC5.6@30.27,9.3 30.278,9.292 30.997,9.292 31.167,9.123 v1(31.233,9.123)
  L1 [TOP] w0.381: v1(12.5,23) 12.515,22.985 12.565,22.985 12.8,22.75 C56.2@12.8,22.075 13.475,22.075 ; G1.4@14.3,22.9 G1.4@14.3,22.95 ; C2.2@26.371,18.225 C1.2@27.529,18.225 ; C1.2@27.56,18.215 v1@28.163,18.215 ; v1(31.406,19.295) 31.41,19.3 31.41,20.808 IC4.3@31.415,20.812 ; IC4.7@32.685,15.388 32.685,16.635 32.7,16.65 v1(32.7,16.7) ; R13.2@33.775,22.9 33.787,22.887 33.787,22.071 v1(33.8,22.059) ; v1(33.95,12.85) 34,12.9 34,13.425 C16.1@33.975,13.45 33.965,13.46 33.965,15.378 IC4.8@33.955,15.388 ; R14.1@37.075,22.9 37.1,22.875 v1(37.1,21.924) ; v1(37.85,14.6) 37.875,14.625 R9.1@38.9,14.625 ; IC8.A9@56.8,19 58.775,19 C35.1@58.8,19.025 59.575,19.025 v1(59.6,19.05)
  L1 [TOP] w0.508: LED2.2@4.59,17.89 LED2.2@4.6,17.9 ; TP1.1@7.625,6.125 7.631,6.131 8.531,6.131 v1(8.65,6.25) ; 13.475,22.075 14.3,22.9 G1.1@14.3,21.05 ; G1.4@14.3,22.95 14.325,22.975 v1(15.1,22.975) ; D1.2@27.1,22.7 v1(27.7,22.7)
  L1 [TOP] w0.762: v1(4.59,16.817) LED2.2@4.59,17.89
  L4 [BOTTOM] w0.203: C12.2@13.75,11.275 13.783,11.308 13.783,11.992 v1(13.817,12.025) ; v1(14.824,9.945) 14.824,10.026 14.826,10.026 14.876,10.076 14.876,10.077 14.95,10.152 14.95,10.394 U2.3@14.968,10.412 ; U2.3@14.932,10.447 14.935,10.45 U2.3@14.95,10.45 ; C42.2@20.5,9.725 20.55,9.725 20.698,9.873 C42.2@20.698,9.923 ; v1@20.976,10.201 v1@21.1,10.201 ; v1(21.1,10.25) v1@21.151,10.25 ; C43.2@21.527,9.873 21.602,9.873 C43.2@21.75,9.725
  L4 [BOTTOM] w0.254: R11.1@11.7,21.85 11.75,21.85 11.873,21.973 11.873,22.023 12.498,22.648 ; 12.499,22.676 13.127,22.048 13.127,21.998 13.248,21.877 R12.1@13.298,21.877 ; 12.5,22.727 v1(12.5,23) ; v1(12.6,14.9) 12.675,14.975 C15.1@12.675,15.6 12.748,15.673 12.748,16.16 12.877,16.289 12.877,16.639 IC3.5@12.9,16.662 ; R12.1@13.181,21.995 R12.1@13.298,21.877 ; R12.1@13.3,21.875 R12.1@13.298,21.877 ; R3.1@24.725,12.55 v1(25.5,12.55) ; U1.4@32.076,6.721 32.231,6.721 32.725,7.216 v1@32.725,7.535 ; U1.3@32.076,7.371 32.237,7.532 32.573,7.532 32.633,7.593 v1(32.7,7.593) ; v1(45.375,17.85) R30.1@45.9,17.85 ; v1(49.09,17.116) 49.129,17.155 49.129,17.289 49.147,17.307 49.147,17.847 R29.1@49.15,17.85
  L4 [BOTTOM] w0.381: v1(18.211,11.909) 18.211,11.941 18.34,12.07 18.34,12.415 18.4,12.475 C3.2@18.45,12.475 ; C6.2@18.618,19.875 C5.2@19.8,19.875 19.802,19.877 19.802,20.537 v1(19.796,20.543) ; C42.2@20.698,9.923 v1@20.976,10.201 ; v1@21.151,10.25 C43.2@21.527,9.873 ; v1(46.8,11.8) 47.425,11.8 C14.2@47.45,11.775 IC2.5@47.45,13.5
  L4 [BOTTOM] w0.508: C57.2@15.1,22.075 v1(15.1,22.975) ; C3.2@18.45,12.475 C4.2@19.65,12.475
  other v1: 6.9,16.2 7.95,16.2 9,16.2 10,16.2
+3V3_IN: F1.1 P1.1 | length 0.6
  L4 [BOTTOM] w0.185: P1.1@7.982,24.792 P1.1@8.415,25.225
+5V: C32.1 C36.2 C59.2 F2.2 IC8.A6 IC8.F4 K3.1 L5.2 L6.1 TP7.1 | length 7.7
  L1 [TOP] w0.381: TP7.1@7.65,3.25 7.7,3.3 v1(7.7,4.15) ; v1(50.15,16.9) 50.175,16.875 C36.2@50.95,16.875 ; C36.2@50.947,16.875 53.925,16.875 IC8.F4@54.3,16.5 ; v1(55.229,21.38) 55.227,21.378 55.227,20.652 C32.1@55.225,20.65 55.225,19.075 IC8.A6@55.3,19
  other v1: 34.448,0.839 43.345,0.889 34.444,1.669 43.352,1.848 1.75,16.25 2.75,16.25 1.75,17.25 2.75,17.25
+5V_IN: F2.1 P1.2 P1.4
  other v1: 3.95,22.95 4.95,22.95
+HV: C44.2 C45.2 IC8.P6 K3.2 | length 11.5
  L1 [TOP] w0.185: v1(55.25,11.432) 55.297,11.479 55.297,12.497 IC8.P6@55.3,12.5
  L4 [BOTTOM] w0.762: C44.2@55.25,9.548 v1(55.25,11.432)
  L4 [BOTTOM] w1.016: C45.2@52.65,9.548 55.25,9.548 55.274,9.524 57.726,9.524 57.75,9.5 58.817,9.5 60.36,7.957 K3.2@60.36,7.95 ; K3.2@60.255,7.845 K3.2@60.35,7.75
-HV: C54.1 C55.1 IC8.P9 K4.2 | length 10.6
  L1 [TOP] w0.185: IC8.P9@56.8,12.5 57.182,12.118 57.182,11.709 v1(57.242,11.648)
  L4 [BOTTOM] w0.762: v1(57.242,11.648) 57.13,11.761 57.13,12.071 57.559,12.5 57.75,12.5
  L4 [BOTTOM] w1.016: C55.1@52.7,13.3 C54.1@55.2,13.3 56.33,13.3 57.13,12.5 57.559,12.5 ; 57.75,12.5 59.16,12.5 K4.2@60.36,11.3
ADC_CLK: IC1.37 IC7.1 TP23.1 | length 28.7
  L1 [TOP] w0.185: IC7.1@23.785,5.1 23.788,5.103 24.716,5.103 v1(24.719,5.106)
  L1 [TOP] w0.203: v1(13.192,7.894) 13.146,7.939 13.146,15.086 13.154,15.094 13.154,17.178 TP23.1@13.131,17.2 13.131,17.206 14.672,18.747 15.56,18.747 15.93,19.117 16.578,19.117 16.748,18.947 17.247,18.947 17.277,18.977 17.577,18.977 IC1.37@17.6,19
  L4 [BOTTOM] w0.203: v1(13.192,7.894) 13.156,7.894 13.124,7.861 14.889,7.861 15.75,7 17.55,7 19.7,4.85 22.041,4.85 22.297,5.106 v1(24.719,5.106)
ADC_CS: IC7.4 TP31.1 | length 4.3
  L1 [TOP] w0.185: IC7.4@23.738,6.596 24.539,6.596 24.543,6.6 24.957,6.6 24.961,6.596 26.646,6.596 26.842,6.4 TP31.1@28,6.4
ADC_SCLK: IC7.5 TP30.1 | length 3.4
  L1 [TOP] w0.185: IC7.5@23.738,7.104 26.104,7.104 26.332,7.332 26.832,7.332 TP30.1@26.95,7.45
ADC_SDIO: IC7.6 TP29.1 | length 1.6
  L1 [TOP] w0.185: IC7.6@23.738,7.612 24.5,7.612 24.988,8.1 TP29.1@25.1,8.1
BT_TRIG: IC1.31 P1.8 R21.2 | length 31.3
  L1 [TOP] w0.203: R21.2@10.4,8.925 v1(10.4,9.7) ; P1.8@16.035,27.765 16.035,27.665 17.15,26.55 19.4,26.55 19.8,26.15 19.8,22.9 20.331,22.369 20.331,21.462 20.732,21.06 v1(20.732,21.038) 20.777,20.994 20.777,19.723 IC1.31@20.8,19.7
  L4 [BOTTOM] w0.203: v1(10.4,9.7) 10.4,11.9 11.675,13.175 14.875,13.175 16.925,15.225 16.925,20.054 17.959,21.087 19.974,21.087 20.024,21.038 v1(20.732,21.038)
BT_USER: IC1.38 P1.10 R26.2 | length 21.7
  L1 [TOP] w0.185: v1@10.4,14.25 v1(10.4,14.3)
  L1 [TOP] w0.203: R26.2@10.4,13.275 v1@10.4,14.25 ; v1(16.319,18.613) 16.399,18.613 16.512,18.5 IC1.38@17.6,18.5
  L4 [BOTTOM] w0.203: v1(10.4,14.3) 14.7,14.3 15.208,14.808 15.208,17.52 15.715,18.027 15.715,18.062 16.266,18.613 v1(16.319,18.613) ; v1@16.292,18.64 16.365,18.712 16.365,19.323 16.467,19.424 16.467,22.767 17.2,23.5 17.2,26.39 P1.10@18.575,27.765
D2: IC1.10 IC7.11 | length 3.8
  L1 [TOP] w0.203: IC7.11@22.112,9.238 22.112,10.062 22.8,10.75 IC1.10@22.8,12.8
D3: IC1.9 IC7.12 | length 3.9
  L1 [TOP] w0.203: IC7.12@21.604,9.238 21.604,10.454 22.3,11.15 22.3,11.509 22.3,11.923 ; 22.3,11.923 IC1.9@22.3,12.8
D4: IC1.6 IC7.14 | length 3.7
  L1 [TOP] w0.203: IC7.14@20.588,9.238 20.588,10.453 20.588,11.394 20.803,11.608 20.803,12.082 20.8,12.084 IC1.6@20.8,12.8
D5: IC1.4 IC7.15 | length 3.8
  L1 [TOP] w0.203: IC1.4@19.8,12.8 19.8,12.113 19.712,12.026 19.712,11.238 20.105,10.845 IC7.15@20.105,9.238
D6: IC1.3 IC7.16 | length 3.7
  L1 [TOP] w0.203: IC1.3@19.3,12.8 19.3,10.85 19.597,10.553 19.597,10.053 IC7.16@19.597,9.238
D7: IC1.2 IC7.17 | length 4.3
  L1 [TOP] w0.203: IC1.2@18.8,12.8 18.8,12.157 18.8,11.743 18.8,9.95 18.962,9.788 18.962,9.538 IC7.17@18.962,8.603
D8: IC1.48 IC7.18 | length 6.4
  L1 [TOP] w0.203: IC1.48@17.6,13.5 17.6,8.8 18.305,8.095 IC7.18@18.962,8.095
D9: IC1.47 IC7.19 | length 8.3
  L1 [TOP] w0.203: IC1.47@17.6,14 17.567,13.967 17.031,13.967 16.883,13.819 16.883,8.867 18.138,7.612 IC7.19@18.962,7.612
D10: IC1.46 IC7.20 | length 10.2
  L1 [TOP] w0.203: IC1.46@17.6,14.5 16.8,14.5 16.341,14.041 16.341,8.459 17.696,7.104 IC7.20@18.962,7.104
D11: IC1.45 IC7.21 | length 12.7
  L1 [TOP] w0.203: IC1.45@17.6,15 16.15,15 15.334,14.184 15.334,8.566 17.304,6.596 IC7.21@18.962,6.596
DAC_CS: IC1.13 IC5.2 TP4.1 | length 5.5
  L1 [TOP] w0.203: IC1.13@24.5,13.5 24.5,12.5 24.875,12.125 25.225,12.125 TP4.1@25.8,11.55 26.296,11.054 26.296,10.204 26.7,9.8 IC5.2@27.4,9.8
dac_g: C41.2 IC5.8 IC6.15 TP5.1 | length 9.8
  L1 [TOP] w0.185: IC5.8@30.27,10.3 30.555,10.3 30.672,10.417 30.672,10.475 30.935,10.738 32.746,10.738 33.183,10.3 TP5.1@33.35,10.3 35,10.3 35.625,10.3
  L1 [TOP] w0.203: 35.625,10.3 35.8,10.475 38.175,10.475 38.75,9.9 38.75,9.343 IC6.15@38.755,9.338
DAC_MOSI: IC1.11 IC5.4 TP2.1 | length 6.9
  L1 [TOP] w0.203: IC1.11@23.3,12.8 23.3,10.897 23.65,10.547 TP2.1@23.65,10.45 25.298,8.802 25.391,8.802 25.392,8.8 IC5.4@27.4,8.8
DAC_SCLK: IC1.12 IC5.3 TP3.1 | length 5.6
  L1 [TOP] w0.203: IC1.12@23.8,12.8 23.8,11.85 26.35,9.3 IC5.3@27.4,9.3
DCLK: IC1.44 IC7.22 | length 15.2
  L1 [TOP] w0.203: IC1.44@17.6,15.5 15.9,15.5 14.32,13.92 14.32,8.13 14.85,7.6 16.36,6.09 IC7.22@18.96,6.09
DONE: IC1.7 P1.16 R4.1 | length 41.9
  L1 [TOP] w0.185: v1(21.125,11.12) 21.125,11.205 21.3,11.38 IC1.7@21.3,12.8
  L1 [TOP] w0.203: P1.16@26.195,27.765 26.447,27.513 26.447,26.696 27.5,25.642 27.5,24.5 28.75,23.25 28.75,12.8 v1(28.735,12.785) ; v1(37.25,18.1) 37.25,19.55 38.025,20.325 R4.1@38.9,20.325
  L4 [BOTTOM] w0.203: v1(21.125,11.12) 21.602,10.644 24.994,10.644 27.135,12.785 v1(28.735,12.785) 29.521,12 30.95,12 34.6,15.65 34.6,16.75 35.95,18.1 v1(37.25,18.1)
EA_CLK: IC1.36 P1.29 | length 37.5
  L1 [TOP] w0.185: v1(19.85,28.6) 20.5,29.25 41.87,29.25 42.65,28.47 42.65,26.55 P1.29@43.975,25.225
  L1 [TOP] w0.203: v1(17.359,21.833) 18.3,20.893 IC1.36@18.3,19.7
  L4 [BOTTOM] w0.203: v1(17.359,21.833) 17.359,21.903 17.768,22.312 17.768,22.829 19.85,24.911 v1(19.85,28.6)
F_CS: IC1.16 IC4.1 P1.26 R13.1 | length 24.8
  L1 [TOP] w0.203: IC1.16@24.5,15 25.761,15 25.832,14.929 26.299,14.929 v1(26.35,14.879) ; v1(33.95,19.1) 33.95,20.807 IC4.1@33.955,20.812 ; IC4.1@33.955,20.812 34.63,20.813 34.825,21.007 R13.1@34.825,22.9 34.825,23.83 35.15,24.155 35.15,26.15 35.55,26.55 37.68,26.55 P1.26@38.895,27.765
  L4 [BOTTOM] w0.203: v1(26.35,14.879) 31.694,14.879 33.947,17.132 33.947,19.097 v1(33.95,19.1)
